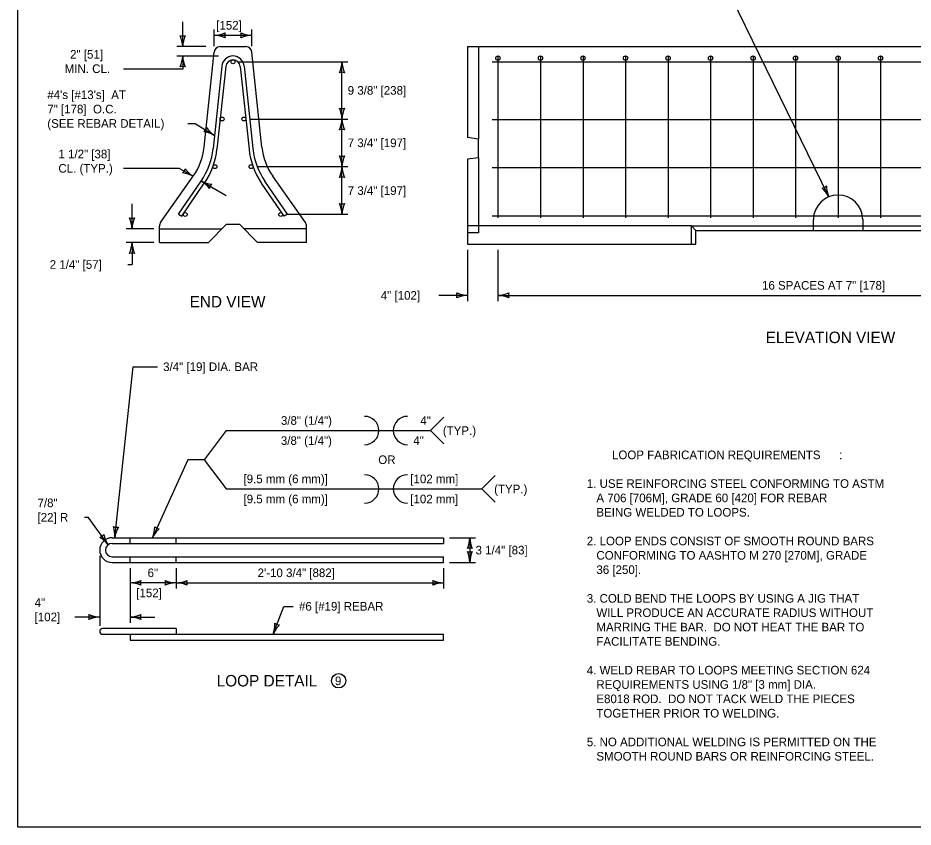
# Model space of a CAD drawing. Extents: x 49991.4 to 50021, y 49987.6 to 50011.4.
# Drawn here: x 49999.38 to 50005.62, y 49987.8 to 49993.44 of the extents above; entities that cross this region are included whole.
import ezdxf

# ---------------------------------------------------------------- set-up
doc = ezdxf.new("R2010")
doc.units = 0
for name, color, linetype in [('Level 1', 7, 'Continuous'), ('Level 2', 7, 'Continuous'), ('Level 3', 7, 'Continuous'), ('Level 4', 7, 'Continuous')]:
    doc.layers.add(name, color=color, linetype=linetype)

msp = doc.modelspace()

# ---------------------------------------------------------------- linework, layer by layer
at = {"layer": 'Level 1'}
for p, q in [((50000.7929, 49993.2368), (50000.9725, 49993.2368)), ((50002.518, 49993.2368), (50007.607, 49993.2368)), ((50002.518, 49993.2368), (50002.518, 49992.603)), ((50000.681, 49992.5359), (50000.7511, 49993.1992)), ((50001.0844, 49992.5359), (50001.0143, 49993.1992)), ((50002.7296, 49993.1714), (50002.7296, 49992.0449)), ((50003.0259, 49993.1714), (50003.0259, 49992.0449)), ((50003.3223, 49993.1714), (50003.3223, 49992.0449)), ((50003.6186, 49993.1714), (50003.6186, 49992.0449)), ((50003.915, 49993.1714), (50003.915, 49992.0449)), ((50004.2113, 49993.1714), (50004.2113, 49992.0449)), ((50004.5077, 49993.1714), (50004.5077, 49992.0449)), ((50004.804, 49993.1714), (50004.804, 49992.0449)), ((50005.1003, 49993.1714), (50005.1003, 49992.0449)), ((50005.3967, 49993.1714), (50005.3967, 49992.0449)), ((50000.8049, 49993.1007), (50000.7443, 49992.5258)), ((50000.9605, 49993.1007), (50001.0211, 49992.5258)), ((50002.6881, 49993.1301), (50007.5129, 49993.1301)), ((50000.8317, 49993.0983), (50000.771, 49992.523)), ((50000.9337, 49993.0983), (50000.9944, 49992.523)), ((50002.6881, 49992.7278), (50007.5129, 49992.7278)), ((50002.5934, 49992.5915), (50002.518, 49992.603)), ((50002.5934, 49992.4629), (50002.5934, 49992.5915)), ((50002.5934, 49992.4629), (50002.518, 49992.4515)), ((50002.518, 49992.4515), (50002.518, 49991.86)), ((50007.5129, 49992.3931), (50002.6881, 49992.3931)), ((50000.3782, 49992.0104), (50000.6059, 49992.3352)), ((50000.5033, 49992.0703), (50000.6607, 49992.2994)), ((50001.2621, 49992.0703), (50001.1047, 49992.2994)), ((50001.3872, 49992.0104), (50001.1595, 49992.3352)), ((50000.5254, 49992.0551), (50000.6829, 49992.2842)), ((50001.24, 49992.0551), (50001.0825, 49992.2842)), ((50000.5033, 49992.0703), (50000.5254, 49992.0551)), ((50001.2621, 49992.0703), (50001.24, 49992.0551)), ((50002.6881, 49992.0584), (50007.5129, 49992.0584)), ((50000.3706, 49991.8718), (50000.3706, 49991.9863)), ((50000.7115, 49991.8718), (50000.8371, 49991.9995)), ((50000.8371, 49991.9995), (50000.9283, 49991.9995)), ((50001.0539, 49991.8718), (50000.9283, 49991.9995)), ((50001.3948, 49991.8718), (50001.3948, 49991.9863)), ((50004.0777, 49991.9885), (50006.1232, 49991.9885)), ((50004.0777, 49991.86), (50004.0777, 49991.9885)), ((50004.0777, 49991.9885), (50004.1097, 49991.9565)), ((50004.9281, 49991.9565), (50004.9281, 49992.0327)), ((50005.2728, 49992.0327), (50005.2728, 49991.9565)), ((50004.1097, 49991.9565), (50006.0912, 49991.9565)), ((50004.1097, 49991.86), (50004.1097, 49991.9565)), ((50000.3706, 49991.8718), (50000.7115, 49991.8718)), ((50001.3948, 49991.8718), (50001.0539, 49991.8718)), ((50002.518, 49991.86), (50004.1097, 49991.86)), ((50000.0402, 49989.8151), (50002.351, 49989.8151)), ((50000.4861, 49989.7751), (50000.4861, 49989.8151)), ((50002.351, 49989.8151), (50002.351, 49989.7751)), ((50000.0402, 49989.7751), (50002.351, 49989.7751)), ((50000.0402, 49989.6821), (50002.351, 49989.6821)), ((50000.4861, 49989.6421), (50000.4861, 49989.6821)), ((50002.351, 49989.6421), (50002.351, 49989.6821)), ((50000.0402, 49989.6421), (50002.351, 49989.6421)), ((50000.4861, 49989.1822), (49999.9738, 49989.1822)), ((50000.4861, 49989.1822), (50000.4861, 49989.1421)), ((49999.9738, 49989.1421), (50002.351, 49989.1421)), ((50000.165, 49989.1421), (50000.165, 49989.102)), ((50002.351, 49989.102), (50002.351, 49989.1421)), ((50000.165, 49989.102), (50002.351, 49989.102))]:
    msp.add_line(p, q, dxfattribs=at)
msp.add_lwpolyline([(49999.3835, 49998.9992), (50016.7501, 49998.9992), (50016.7501, 49987.7988), (49999.3835, 49987.7988)], close=True, dxfattribs=at)
for centre, radius in [((50002.7296, 49993.1564), 0.015), ((50003.0259, 49993.1564), 0.015), ((50003.3223, 49993.1564), 0.015), ((50003.6186, 49993.1564), 0.015), ((50003.915, 49993.1564), 0.015), ((50004.2113, 49993.1564), 0.015), ((50004.5077, 49993.1564), 0.015), ((50004.804, 49993.1564), 0.015), ((50005.1003, 49993.1564), 0.015), ((50005.3967, 49993.1564), 0.015), ((50000.8827, 49993.1311), 0.0134), ((50000.8066, 49992.7324), 0.0134), ((50000.9588, 49992.7324), 0.0134), ((50000.757, 49992.4004), 0.0134), ((50001.0084, 49992.4004), 0.0134), ((50000.5501, 49992.0673), 0.0134), ((50001.2153, 49992.0673), 0.0134)]:
    msp.add_circle(centre, radius, dxfattribs=at)
for centre, radius, start, end in [((50000.7929, 49993.1948), 0.042, 90, 173.97247), ((50000.9725, 49993.1948), 0.042, 6.02753, 90), ((50000.8827, 49993.0932), 0.0782, 5.53181, 174.46819), ((50000.8827, 49993.0933), 0.0512, 5.58715, 174.41285), ((50000.2553, 49992.5809), 0.4281, 324.97771, 353.97247), ((50000.2568, 49992.5771), 0.4902, 325.491, 353.991), ((50000.2568, 49992.5771), 0.5171, 325.491, 353.991), ((50001.5086, 49992.5771), 0.5171, 186.009, 214.509), ((50001.5086, 49992.5771), 0.4902, 186.009, 214.509), ((50001.5101, 49992.5809), 0.4281, 186.02753, 215.02229), ((50005.1004, 49992.0301), 0.1724, 0.88708, 179.11292), ((50000.4126, 49991.9863), 0.042, 144.97771, 180), ((50001.3528, 49991.9863), 0.042, 0, 35.02229), ((50000.0402, 49989.7286), 0.0865, 90, 270), ((50000.0402, 49989.7286), 0.0465, 90, 270), ((49999.9738, 49989.1621), 0.0201, 90, 270)]:
    msp.add_arc(centre, radius, start, end, dxfattribs=at)
at = {"layer": 'Level 2'}
msp.add_circle((50001.6194, 49988.8184), 0.05, dxfattribs=at)
at = {"layer": 'Level 3'}
for p, q in [((50005.0362, 49992.19), (50004.3296, 49993.635)), ((50000.532, 49993.2367), (50000.532, 49993.4102)), ((50000.7511, 49993.2392), (50000.7511, 49993.3556)), ((50001.0143, 49993.2392), (50001.0143, 49993.3556)), ((50000.7511, 49993.3156), (50001.0143, 49993.3156)), ((50000.6929, 49993.2368), (50000.492, 49993.2368)), ((50000.7827, 49993.1713), (50000.492, 49993.1713)), ((50000.532, 49993.1713), (50000.532, 49993.0806)), ((50000.9227, 49993.1311), (50001.6822, 49993.1311)), ((50001.6422, 49992.7324), (50001.6422, 49993.1311)), ((50000.532, 49993.0806), (50000.119, 49993.0806)), ((50000.9988, 49992.7324), (50001.6822, 49992.7324)), ((50001.6422, 49992.4004), (50001.6422, 49992.7324)), ((50000.569, 49992.7013), (50000.62, 49992.7013)), ((50000.62, 49992.7013), (50000.7541, 49992.6184)), ((50000.5105, 49992.3884), (50000.119, 49992.3884)), ((50000.5105, 49992.3884), (50000.6059, 49992.3331)), ((50001.0484, 49992.4004), (50001.6822, 49992.4004)), ((50001.6422, 49992.0673), (50001.6422, 49992.4004)), ((50000.6624, 49992.3003), (50000.835, 49992.2002)), ((50000.1788, 49991.9676), (50000.1792, 49992.141)), ((50001.6822, 49992.0673), (50001.2553, 49992.0673)), ((50000.3306, 49991.9676), (50000.1388, 49991.9676)), ((50000.3306, 49991.8718), (50000.1388, 49991.8718)), ((50000.1788, 49991.8718), (50000.1788, 49991.7185)), ((50002.518, 49991.82), (50002.518, 49991.4634)), ((50002.7297, 49991.82), (50002.7297, 49991.4634)), ((50000.1496, 49991.7185), (50000.1788, 49991.7185)), ((50002.518, 49991.5034), (50002.318, 49991.5034)), ((50002.7297, 49991.5034), (50007.4713, 49991.5034)), ((50002.2589, 49990.5617), (50002.3523, 49990.6551)), ((50000.8358, 49990.5617), (50002.2589, 49990.5617)), ((50002.2589, 49990.5617), (50002.3523, 49990.4685)), ((50000.5688, 49990.3583), (50000.3215, 49989.8152)), ((50000.6814, 49990.3583), (50000.5688, 49990.3583)), ((50002.6165, 49990.1549), (50002.7099, 49990.2483)), ((50000.8358, 49990.1549), (50002.6165, 49990.1549)), ((50002.6165, 49990.1549), (50002.7099, 49990.0617)), ((49999.8467, 49989.9576), (49999.8729, 49989.9576)), ((50000.0127, 49989.7661), (49999.8729, 49989.9576)), ((50002.391, 49989.8152), (50002.5734, 49989.8152)), ((50002.5334, 49989.8152), (50002.5334, 49989.6421)), ((49999.9537, 49989.6886), (49999.9537, 49989.2021)), ((50002.391, 49989.6421), (50002.5734, 49989.6421)), ((50000.165, 49989.6021), (50000.165, 49989.2222)), ((50000.486, 49989.6021), (50000.486, 49989.4606)), ((50002.3508, 49989.6021), (50002.3508, 49989.4606)), ((50000.486, 49989.5006), (50000.165, 49989.5006)), ((50000.486, 49989.5006), (50002.3508, 49989.5006)), ((49999.7803, 49989.263), (49999.9537, 49989.263)), ((50000.165, 49989.2622), (50000.3385, 49989.2622))]:
    msp.add_line(p, q, dxfattribs=at)
for points in [[(50000.0587, 49989.8151), (50000.1866, 49991.0064), (50000.3558, 49991.0064)], [(50000.8358, 49990.5617), (50000.6814, 49990.3583), (50000.8358, 49990.1549)], [(50001.1625, 49989.1421), (50001.2376, 49989.3367), (50001.3026, 49989.3367)]]:
    msp.add_lwpolyline(points, dxfattribs=at)
for centre, radius, start, end in [((50000.532, 49993.365), 0.0548, 252.13882, 287.86118), ((50000.2993, 49993.2252), 0.233, 2.82731, 22.07716), ((50000.7542, 49993.2276), 0.2223, 157.45601, 177.63952), ((50000.7396, 49993.5483), 0.233, 272.82731, 292.07716), ((50000.742, 49993.0935), 0.2223, 67.45601, 87.63952), ((50000.8794, 49993.3156), 0.0548, 162.13882, 197.86118), ((50001.0234, 49993.5377), 0.2223, 247.45601, 267.63952), ((50000.8861, 49993.3156), 0.0548, 342.13882, 17.86118), ((50001.0258, 49993.0829), 0.233, 92.82731, 112.07716), ((50000.3099, 49993.1805), 0.2223, 337.45601, 357.63952), ((50000.7648, 49993.1828), 0.233, 182.82731, 202.07716), ((50001.4201, 49993.1403), 0.2223, 337.45601, 357.63952), ((50001.8749, 49993.1426), 0.233, 182.82731, 202.07716), ((50000.532, 49993.0431), 0.0548, 72.13882, 107.86118), ((50001.6422, 49993.0029), 0.0548, 72.13882, 107.86118), ((50001.6422, 49992.8606), 0.0548, 252.13882, 287.86118), ((50001.4095, 49992.7209), 0.233, 2.82731, 22.07716), ((50001.8643, 49992.7232), 0.2223, 157.45601, 177.63952), ((50001.4201, 49992.7415), 0.2223, 337.45601, 357.63952), ((50001.8749, 49992.7439), 0.233, 182.82731, 202.07716), ((50000.645, 49992.6858), 0.0548, 310.40399, 346.12635), ((50000.8787, 49992.8025), 0.2223, 215.72118, 235.90469), ((50000.6414, 49992.4144), 0.233, 61.09248, 80.34233), ((50001.6422, 49992.6042), 0.0548, 72.13882, 107.86118), ((50001.6422, 49992.5286), 0.0548, 252.13882, 287.86118), ((50001.4095, 49992.3889), 0.233, 2.82731, 22.07716), ((50001.8643, 49992.3912), 0.2223, 157.45601, 177.63952), ((50000.495, 49992.3974), 0.0548, 312.03356, 347.75592), ((50000.4991, 49992.126), 0.233, 62.72205, 81.9719), ((50000.7253, 49992.5207), 0.2223, 217.35075, 237.53426), ((50001.4201, 49992.4095), 0.2223, 337.45601, 357.63952), ((50001.8749, 49992.4119), 0.233, 182.82731, 202.07716), ((50000.5415, 49992.1138), 0.2223, 37.35075, 57.53426), ((50000.7676, 49992.5085), 0.233, 242.72205, 261.9719), ((50001.6422, 49992.2722), 0.0548, 72.13882, 107.86118), ((50000.7717, 49992.2371), 0.0548, 132.03356, 167.75592), ((50004.9807, 49992.3056), 0.0548, 277.75088, 313.47324), ((50004.8313, 49992.079), 0.233, 28.43938, 47.68923), ((50005.2404, 49992.2778), 0.2223, 183.06808, 203.25158), ((50001.6422, 49992.1955), 0.0548, 252.13882, 287.86118), ((50001.4095, 49992.0558), 0.233, 2.82731, 22.07716), ((50001.8643, 49992.0581), 0.2223, 157.45601, 177.63952), ((50000.1791, 49992.0958), 0.0548, 252.00662, 287.72898), ((49999.9461, 49991.9566), 0.233, 2.69511, 21.94496), ((50000.401, 49991.9579), 0.2223, 157.32381, 177.50732), ((49999.9567, 49991.8805), 0.2223, 337.56516, 357.74867), ((50000.4115, 49991.8837), 0.233, 182.93646, 202.18631), ((50000.1791, 49991.7436), 0.0548, 72.24797, 107.97033), ((50002.5272, 49991.7256), 0.2223, 247.45601, 267.63952), ((50002.3898, 49991.5034), 0.0548, 342.13882, 17.86118), ((50002.5295, 49991.2707), 0.233, 92.82731, 112.07716), ((50002.7182, 49991.7361), 0.233, 272.82731, 292.07716), ((50002.7205, 49991.2813), 0.2223, 67.45601, 87.63952), ((50002.8579, 49991.5034), 0.0548, 162.13882, 197.86118), ((50001.8001, 49990.5617), 0.0989, 270, 90), ((50002.0989, 49990.5617), 0.0989, 90, 270), ((50001.8001, 49990.1549), 0.0989, 270, 90), ((50002.0989, 49990.1549), 0.0989, 90, 270), ((50000.0724, 49989.9426), 0.0548, 246.01042, 281.73278), ((49999.8261, 49989.8285), 0.233, 356.69891, 15.94876), ((50000.2786, 49989.7823), 0.2223, 151.32761, 171.51112), ((50000.1049, 49989.9011), 0.233, 338.34765, 357.5975), ((50000.5199, 49989.7148), 0.2223, 132.97635, 153.15986), ((50000.3746, 49989.9319), 0.0548, 227.65916, 263.38152), ((49999.937, 49989.8696), 0.0548, 288.31572, 324.03808), ((49999.8316, 49989.6194), 0.233, 39.00421, 58.25406), ((50000.1974, 49989.8898), 0.2223, 193.63291, 213.81642), ((50002.3113, 49989.8243), 0.2223, 337.45601, 357.63952), ((50002.7662, 49989.8267), 0.233, 182.82731, 202.07716), ((50002.5334, 49989.687), 0.0548, 72.13882, 107.86118), ((50002.5334, 49989.7703), 0.0548, 252.13882, 287.86118), ((50002.3007, 49989.6306), 0.233, 2.82731, 22.07716), ((50002.7556, 49989.633), 0.2223, 157.45601, 177.63952), ((50000.1535, 49989.7333), 0.233, 272.82731, 292.07716), ((50000.1559, 49989.2784), 0.2223, 67.45601, 87.63952), ((50000.2933, 49989.5006), 0.0548, 162.13882, 197.86118), ((50000.4951, 49989.7227), 0.2223, 247.45601, 267.63952), ((50000.3578, 49989.5006), 0.0548, 342.13882, 17.86118), ((50000.4975, 49989.2678), 0.233, 92.82731, 112.07716), ((50000.4745, 49989.7333), 0.233, 272.82731, 292.07716), ((50000.4745, 49989.7333), 0.233, 272.82731, 292.07716), ((50000.4768, 49989.2784), 0.2223, 67.45601, 87.63952), ((50000.4768, 49989.2784), 0.2223, 67.45601, 87.63952), ((50000.6142, 49989.5006), 0.0548, 162.13882, 197.86118), ((50000.6142, 49989.5006), 0.0548, 162.13882, 197.86118), ((50002.36, 49989.7227), 0.2223, 247.45601, 267.63952), ((50002.2226, 49989.5006), 0.0548, 342.13882, 17.86118), ((50002.3623, 49989.2678), 0.233, 92.82731, 112.07716), ((49999.9629, 49989.4851), 0.2223, 247.45601, 267.63952), ((49999.8255, 49989.263), 0.0548, 342.13882, 17.86118), ((49999.9652, 49989.0303), 0.233, 92.82731, 112.07716), ((50000.1535, 49989.4949), 0.233, 272.82731, 292.07716), ((50000.1559, 49989.0401), 0.2223, 67.45601, 87.63952), ((50000.2933, 49989.2622), 0.0548, 162.13882, 197.86118), ((50000.9412, 49989.2151), 0.233, 341.72472, 0.97457), ((50001.3664, 49989.0536), 0.2223, 136.35342, 156.53693), ((50001.2086, 49989.2617), 0.0548, 231.03623, 266.75859)]:
    msp.add_arc(centre, radius, start, end, dxfattribs=at)
at = {"layer": 'Level 4'}
for p, q in [((50002.5934, 49993.2368), (50002.5934, 49992.5915)), ((50002.5934, 49992.4629), (50002.5934, 49991.9404)), ((50004.0777, 49991.9885), (50002.518, 49991.9885)), ((50000.3706, 49991.9676), (50000.8057, 49991.9676)), ((50001.3948, 49991.9676), (50000.9597, 49991.9676)), ((50002.5934, 49991.9404), (50002.518, 49991.9404)), ((50000.165, 49989.7751), (50000.165, 49989.8151)), ((50000.165, 49989.6421), (50000.165, 49989.6821))]:
    msp.add_line(p, q, dxfattribs=at)

# ---------------------------------------------------------------- texts
at = {"layer": 'Level 2'}
for s, height, p in [('[152]', 0.06, (50000.7656, 49993.3556)), ('2" [51] ', 0.06, (49999.7475, 49993.153)), ('MIN. CL. ', 0.06, (49999.7095, 49993.053)), ("#4's [#13's]  AT ", 0.06, (49999.5885, 49992.8713)), ('9 3/8" [238]', 0.06, (50001.6822, 49992.9017)), ('7" [178]  O.C.', 0.06, (49999.5885, 49992.7713)), ('(SEE REBAR DETAIL)', 0.06, (49999.5885, 49992.6713)), ('7 3/4" [197]', 0.06, (50001.6822, 49992.5364)), ('1 1/2" [38]', 0.06, (49999.6659, 49992.4584)), ('CL. (TYP.)', 0.06, (49999.6659, 49992.3584)), ('7 3/4" [197]', 0.06, (50001.6822, 49992.2038)), ('2 1/4" [57]', 0.06, (49999.6051, 49991.6885)), ('16 SPACES AT 7" [178]', 0.06, (50004.57, 49991.5434)), ('END VIEW', 0.08, (50000.5802, 49991.4195)), ('4" [102]', 0.06, (50001.9131, 49991.4734)), ('ELEVATION VIEW', 0.08, (50004.5951, 49991.1709)), ('3/4" [19] DIA. BAR', 0.06, (50000.3958, 49990.9764)), ('3/8" (1/4")', 0.06, (50001.2167, 49990.6017)), ('4" ', 0.06, (50002.1886, 49990.6017)), ('(TYP.)', 0.06, (50002.3452, 49990.5314)), ('3/8" (1/4")', 0.06, (50001.2164, 49990.4617)), ('4"', 0.06, (50002.1392, 49990.4616)), ('LOOP FABRICATION REQUIREMENTS', 0.06, (50003.5245, 49990.3623)), ('OR', 0.06, (50001.8953, 49990.3283)), (':', 0.06, (50005.1072, 49990.3623)), ('[9.5 mm (6 mm)]', 0.06, (50000.9558, 49990.1949)), (' [102 mm]', 0.06, (50002.0964, 49990.1949)), ('(TYP.)', 0.06, (50002.7028, 49990.1245)), ('1. USE REINFORCING STEEL CONFORMING TO ASTM ', 0.06, (50003.3486, 49990.1623)), ('[9.5 mm (6 mm)]', 0.06, (50000.9559, 49990.0549)), (' [102 mm]', 0.06, (50002.0962, 49990.0549)), ('   A 706 [706M], GRADE 60 [420] FOR REBAR ', 0.06, (50003.3486, 49990.0623)), ('7/8"', 0.06, (49999.5202, 49990.0276)), ('[22] R', 0.06, (49999.5202, 49989.9276)), ('   BEING WELDED TO LOOPS.', 0.06, (50003.3486, 49989.9623)), ('2. LOOP ENDS CONSIST OF SMOOTH ROUND BARS ', 0.06, (50003.3486, 49989.7623)), ('3 1/4" [83]', 0.06, (50002.5734, 49989.6986)), ('   CONFORMING TO AASHTO M 270 [270M], GRADE ', 0.06, (50003.3486, 49989.6623)), ('   36 [250].', 0.06, (50003.3486, 49989.5623)), ('6"', 0.06, (50000.2874, 49989.5405)), ('2\'-10 3/4" [882]', 0.06, (50001.0541, 49989.5406)), ('[152]', 0.06, (50000.2084, 49989.4006)), ('3. COLD BEND THE LOOPS BY USING A JIG THAT ', 0.06, (50003.3486, 49989.3623)), ('4" ', 0.06, (49999.4999, 49989.333)), ('#6 [#19] REBAR', 0.06, (50001.3426, 49989.3068)), ('[102]', 0.06, (49999.4999, 49989.233)), ('   WILL PRODUCE AN ACCURATE RADIUS WITHOUT ', 0.06, (50003.3486, 49989.2623)), ('   MARRING THE BAR.  DO NOT HEAT THE BAR TO ', 0.06, (50003.3486, 49989.1623)), ('   FACILITATE BENDING.', 0.06, (50003.3486, 49989.0623)), ('4. WELD REBAR TO LOOPS MEETING SECTION 624', 0.06, (50003.3486, 49988.8623)), ('LOOP DETAIL', 0.08, (50000.7686, 49988.7787)), ('9', 0.06, (50001.5933, 49988.7876)), ('   REQUIREMENTS USING 1/8" [3 mm] DIA. ', 0.06, (50003.3486, 49988.7623)), ('   E8018 ROD.  DO NOT TACK WELD THE PIECES ', 0.06, (50003.3486, 49988.6623)), ('   TOGETHER PRIOR TO WELDING.', 0.06, (50003.3486, 49988.5623)), ('5. NO ADDITIONAL WELDING IS PERMITTED ON THE ', 0.06, (50003.3486, 49988.3623)), ('   SMOOTH ROUND BARS OR REINFORCING STEEL.', 0.06, (50003.3486, 49988.2623))]:
    msp.add_text(s, height=height, dxfattribs=at).set_placement(p)

doc.saveas('drawing.dxf')
